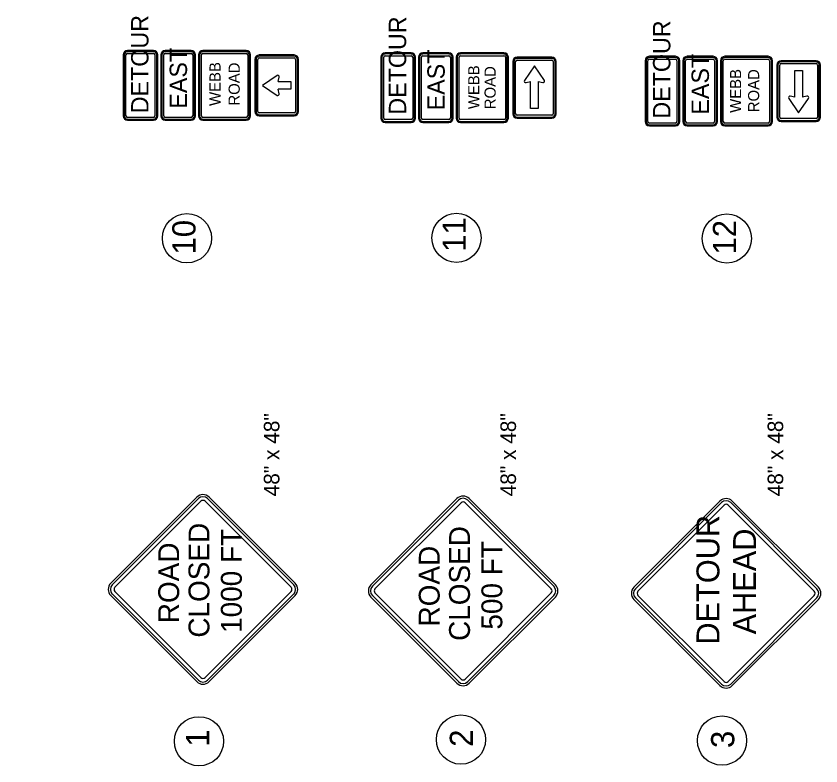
# Model space of a CAD drawing. Extents: x 1123038 to 1172987, y 554419 to 623636.
# Drawn here: x 1123038 to 1128822, y 554419 to 559806 of the extents above; entities that cross this region are included whole.
import ezdxf

# ---------------------------------------------------------------- set-up
doc = ezdxf.new("R2010")
doc.units = 0
doc.layers.add('D_Text_Standard', color=7, linetype='Continuous')
doc.layers.add('Default', color=7, linetype='Continuous')

msp = doc.modelspace()

# ---------------------------------------------------------------- linework, layer by layer
at = {"layer": 'D_Text_Standard'}
for centre in [(1124265.6, 558210), (1126203.5, 558213.5), (1128146.3, 558208.3), (1124352.1, 554596.3), (1126235, 554608.5), (1128111.3, 554601.2)]:
    msp.add_circle(centre, 176.8, dxfattribs=at)
at = {"layer": 'Default'}
for p, q in [((1124025.5, 559558), (1123838, 559558)), ((1124025.5, 559550.2), (1123838, 559550.2)), ((1123838, 559537.1), (1124025.5, 559537.1)), ((1124296.4, 559558), (1124108.9, 559558)), ((1124296.4, 559550.2), (1124108.9, 559550.2)), ((1124108.9, 559537.1), (1124296.4, 559537.1)), ((1124692.2, 559558), (1124379.7, 559558)), ((1124692.2, 559550.2), (1124379.7, 559550.2)), ((1124379.7, 559537.1), (1124692.2, 559537.1)), ((1125877.8, 559541.7), (1125690.3, 559541.7)), ((1125877.8, 559533.9), (1125690.3, 559533.9)), ((1126148.6, 559541.7), (1125961.1, 559541.7)), ((1126148.6, 559533.9), (1125961.1, 559533.9)), ((1126544.4, 559541.7), (1126231.9, 559541.7)), ((1126544.4, 559533.9), (1126231.9, 559533.9)), ((1123806.8, 559526.7), (1123806.8, 559089.2)), ((1123814.6, 559526.7), (1123814.6, 559089.2)), ((1123827.6, 559089.2), (1123827.6, 559526.7)), ((1124035.9, 559526.7), (1124035.9, 559089.2)), ((1124049, 559089.2), (1124049, 559526.7)), ((1124056.8, 559089.2), (1124056.8, 559526.7)), ((1124077.6, 559526.7), (1124077.6, 559089.2)), ((1124085.4, 559526.7), (1124085.4, 559089.2)), ((1124098.4, 559089.2), (1124098.4, 559526.7)), ((1124306.8, 559526.7), (1124306.8, 559089.2)), ((1124319.8, 559089.2), (1124319.8, 559526.7)), ((1124327.6, 559089.2), (1124327.6, 559526.7)), ((1124348.4, 559526.7), (1124348.4, 559089.2)), ((1124356.3, 559526.7), (1124356.3, 559089.2)), ((1124369.3, 559089.2), (1124369.3, 559526.7)), ((1124702.6, 559526.7), (1124702.6, 559089.2)), ((1124715.6, 559089.2), (1124715.6, 559526.7)), ((1124723.4, 559089.2), (1124723.4, 559526.7)), ((1124754.7, 559495.5), (1124754.7, 559120.5)), ((1124762.5, 559495.5), (1124762.5, 559120.5)), ((1124775.5, 559120.5), (1124775.5, 559495.5)), ((1125035.9, 559526.7), (1124785.9, 559526.7)), ((1125035.9, 559518.9), (1124785.9, 559518.9)), ((1124785.9, 559505.9), (1125035.9, 559505.9)), ((1125046.4, 559495.5), (1125046.4, 559120.5)), ((1125059.4, 559120.5), (1125059.4, 559495.5)), ((1125067.2, 559120.5), (1125067.2, 559495.5)), ((1125659, 559510.4), (1125659, 559072.9)), ((1125666.8, 559510.4), (1125666.8, 559072.9)), ((1125679.9, 559072.9), (1125679.9, 559510.4)), ((1125690.3, 559520.8), (1125877.8, 559520.8)), ((1125888.2, 559510.4), (1125888.2, 559072.9)), ((1125901.2, 559072.9), (1125901.2, 559510.4)), ((1125909, 559072.9), (1125909, 559510.4)), ((1125929.9, 559510.4), (1125929.9, 559072.9)), ((1125937.7, 559510.4), (1125937.7, 559072.9)), ((1125950.7, 559072.9), (1125950.7, 559510.4)), ((1125961.1, 559520.8), (1126148.6, 559520.8)), ((1126159, 559510.4), (1126159, 559072.9)), ((1126172, 559072.9), (1126172, 559510.4)), ((1126179.9, 559072.9), (1126179.9, 559510.4)), ((1126200.7, 559510.4), (1126200.7, 559072.9)), ((1126208.5, 559510.4), (1126208.5, 559072.9)), ((1126221.5, 559072.9), (1126221.5, 559510.4)), ((1126231.9, 559520.8), (1126544.4, 559520.8)), ((1126554.9, 559510.4), (1126554.9, 559072.9)), ((1126567.9, 559072.9), (1126567.9, 559510.4)), ((1126575.7, 559072.9), (1126575.7, 559510.4)), ((1126606.9, 559479.2), (1126606.9, 559104.2)), ((1126614.7, 559479.2), (1126614.7, 559104.2)), ((1126627.8, 559104.2), (1126627.8, 559479.2)), ((1126888.2, 559510.4), (1126638.2, 559510.4)), ((1126888.2, 559502.6), (1126638.2, 559502.6)), ((1126638.2, 559489.6), (1126888.2, 559489.6)), ((1126898.6, 559479.2), (1126898.6, 559104.2)), ((1126911.6, 559104.2), (1126911.6, 559479.2)), ((1126919.4, 559104.2), (1126919.4, 559479.2)), ((1127557.9, 559485.9), (1127557.9, 559048.4)), ((1127565.7, 559485.9), (1127565.7, 559048.4)), ((1127578.7, 559048.4), (1127578.7, 559485.9)), ((1127776.6, 559517.2), (1127589.1, 559517.2)), ((1127776.6, 559509.4), (1127589.1, 559509.4)), ((1127589.1, 559496.3), (1127776.6, 559496.3)), ((1127787.1, 559485.9), (1127787.1, 559048.4)), ((1127800.1, 559048.4), (1127800.1, 559485.9)), ((1127807.9, 559048.4), (1127807.9, 559485.9)), ((1127828.7, 559485.9), (1127828.7, 559048.4)), ((1127836.5, 559485.9), (1127836.5, 559048.4)), ((1127849.5, 559048.4), (1127849.5, 559485.9)), ((1128047.5, 559517.2), (1127860, 559517.2)), ((1128047.5, 559509.4), (1127860, 559509.4)), ((1127860, 559496.3), (1128047.5, 559496.3)), ((1128057.9, 559485.9), (1128057.9, 559048.4)), ((1128070.9, 559048.4), (1128070.9, 559485.9)), ((1128078.7, 559048.4), (1128078.7, 559485.9)), ((1128099.5, 559485.9), (1128099.5, 559048.4)), ((1128107.4, 559485.9), (1128107.4, 559048.4)), ((1128120.4, 559048.4), (1128120.4, 559485.9)), ((1128443.3, 559517.2), (1128130.8, 559517.2)), ((1128443.3, 559509.4), (1128130.8, 559509.4)), ((1128130.8, 559496.3), (1128443.3, 559496.3)), ((1128453.7, 559485.9), (1128453.7, 559048.4)), ((1128466.7, 559048.4), (1128466.7, 559485.9)), ((1128474.5, 559048.4), (1128474.5, 559485.9)), ((1128787, 559485.9), (1128537, 559485.9)), ((1128787, 559478.1), (1128537, 559478.1)), ((1126763.2, 559447.9), (1126691.9, 559344.1)), ((1126834.5, 559344.1), (1126763.2, 559447.9)), ((1128505.8, 559454.7), (1128505.8, 559079.7)), ((1128513.6, 559454.7), (1128513.6, 559079.7)), ((1128526.6, 559079.7), (1128526.6, 559454.7)), ((1128537, 559465.1), (1128787, 559465.1)), ((1128634.7, 559415.6), (1128689.4, 559415.6)), ((1128634.7, 559222.9), (1128634.7, 559415.6)), ((1128689.4, 559415.6), (1128689.4, 559222.9)), ((1128797.5, 559454.7), (1128797.5, 559079.7)), ((1128810.5, 559079.7), (1128810.5, 559454.7)), ((1128818.3, 559079.7), (1128818.3, 559454.7)), ((1124913.2, 559379.3), (1124809.4, 559308)), ((1124921.4, 559335.3), (1124928.9, 559368.1)), ((1124809.4, 559308), (1124913.2, 559236.7)), ((1124921.4, 559335.3), (1125012.5, 559335.3)), ((1125012.5, 559335.3), (1125012.5, 559280.6)), ((1126703, 559328.4), (1126735.8, 559335.9)), ((1126735.8, 559143.2), (1126735.8, 559335.9)), ((1126790.5, 559335.9), (1126823.3, 559328.4)), ((1126790.5, 559335.9), (1126790.5, 559143.2)), ((1124928.9, 559247.8), (1124921.4, 559280.6)), ((1125012.5, 559280.6), (1124921.4, 559280.6)), ((1128590.7, 559214.7), (1128662, 559110.9)), ((1128634.7, 559222.9), (1128601.9, 559230.4)), ((1128662, 559110.9), (1128733.4, 559214.7)), ((1128722.2, 559230.4), (1128689.4, 559222.9)), ((1126790.5, 559143.2), (1126735.8, 559143.2)), ((1124025.5, 559078.8), (1123838, 559078.8)), ((1124296.4, 559078.8), (1124108.9, 559078.8)), ((1124692.2, 559078.8), (1124379.7, 559078.8)), ((1125035.9, 559110.1), (1124785.9, 559110.1)), ((1124785.9, 559097), (1125035.9, 559097)), ((1124785.9, 559089.2), (1125035.9, 559089.2)), ((1126888.2, 559093.8), (1126638.2, 559093.8)), ((1126638.2, 559080.7), (1126888.2, 559080.7)), ((1126638.2, 559072.9), (1126888.2, 559072.9)), ((1128787, 559069.3), (1128537, 559069.3)), ((1123838, 559065.8), (1124025.5, 559065.8)), ((1123838, 559058), (1124025.5, 559058)), ((1124108.9, 559065.8), (1124296.4, 559065.8)), ((1124108.9, 559058), (1124296.4, 559058)), ((1124379.7, 559065.8), (1124692.2, 559065.8)), ((1124379.7, 559058), (1124692.2, 559058)), ((1125877.8, 559062.5), (1125690.3, 559062.5)), ((1125690.3, 559049.5), (1125877.8, 559049.5)), ((1125690.3, 559041.7), (1125877.8, 559041.7)), ((1126148.6, 559062.5), (1125961.1, 559062.5)), ((1125961.1, 559049.5), (1126148.6, 559049.5)), ((1125961.1, 559041.7), (1126148.6, 559041.7)), ((1126544.4, 559062.5), (1126231.9, 559062.5)), ((1126231.9, 559049.5), (1126544.4, 559049.5)), ((1126231.9, 559041.7), (1126544.4, 559041.7)), ((1127776.6, 559038), (1127589.1, 559038)), ((1127589.1, 559025), (1127776.6, 559025)), ((1127589.1, 559017.2), (1127776.6, 559017.2)), ((1128047.5, 559038), (1127860, 559038)), ((1127860, 559025), (1128047.5, 559025)), ((1127860, 559017.2), (1128047.5, 559017.2)), ((1128443.3, 559038), (1128130.8, 559038)), ((1128130.8, 559025), (1128443.3, 559025)), ((1128130.8, 559017.2), (1128443.3, 559017.2)), ((1128537, 559056.2), (1128787, 559056.2)), ((1128537, 559048.4), (1128787, 559048.4)), ((1124336.7, 556350.4), (1123718, 555731.7)), ((1125043.8, 555731.7), (1124425.1, 556350.4)), ((1124347.8, 556339.4), (1123729, 555720.7)), ((1123747.5, 555702.3), (1124366.2, 556321)), ((1124395.6, 556321), (1125014.3, 555702.3)), ((1125032.8, 555720.7), (1124414, 556339.4)), ((1126206.4, 556339.5), (1125587.7, 555720.8)), ((1126217.5, 556328.5), (1125598.8, 555709.8)), ((1125617.2, 555691.4), (1126235.9, 556310.1)), ((1126265.4, 556310.1), (1126884.1, 555691.4)), ((1126902.5, 555709.8), (1126283.8, 556328.5)), ((1126913.5, 555720.8), (1126294.8, 556339.5)), ((1128096.7, 556322.1), (1127478, 555703.4)), ((1128107.8, 556311), (1127489.1, 555692.3)), ((1127507.5, 555673.9), (1128126.2, 556292.6)), ((1128155.7, 556292.6), (1128774.4, 555673.9)), ((1128792.8, 555692.3), (1128174.1, 556311)), ((1128803.8, 555703.4), (1128185.1, 556322.1)), ((1123729, 555654.4), (1124347.8, 555035.7)), ((1124366.2, 555054.1), (1123747.5, 555672.8)), ((1125014.3, 555672.8), (1124395.6, 555054.1)), ((1124414, 555035.7), (1125032.8, 555654.4)), ((1126235.9, 555043.2), (1125617.2, 555661.9)), ((1126884.1, 555661.9), (1126265.4, 555043.2)), ((1123718, 555643.3), (1124336.7, 555024.6)), ((1124425.1, 555024.6), (1125043.8, 555643.3)), ((1125587.7, 555632.4), (1126206.4, 555013.7)), ((1125598.8, 555643.5), (1126217.5, 555024.8)), ((1126283.8, 555024.8), (1126902.5, 555643.5)), ((1126294.8, 555013.7), (1126913.5, 555632.4)), ((1127478, 555615), (1128096.7, 554996.3)), ((1127489.1, 555626), (1128107.8, 555007.3)), ((1128126.2, 555025.7), (1127507.5, 555644.4)), ((1128774.4, 555644.4), (1128155.7, 555025.7)), ((1128174.1, 555007.3), (1128792.8, 555626)), ((1128185.1, 554996.3), (1128803.8, 555615))]:
    msp.add_line(p, q, dxfattribs=at)
for centre, radius, start, end in [((1123838, 559526.7), 31.2, 90, 180), ((1123838, 559526.7), 23.4, 90, 180), ((1123838, 559526.7), 10.4, 90, 180), ((1124025.5, 559526.7), 31.2, 0, 90), ((1124025.5, 559526.7), 23.4, 0, 90), ((1124025.5, 559526.7), 10.4, 0, 90), ((1124108.9, 559526.7), 31.2, 90, 180), ((1124108.9, 559526.7), 23.4, 90, 180), ((1124108.9, 559526.7), 10.4, 90, 180), ((1124296.4, 559526.7), 31.2, 0, 90), ((1124296.4, 559526.7), 23.4, 0, 90), ((1124296.4, 559526.7), 10.4, 0, 90), ((1124379.7, 559526.7), 31.2, 90, 180), ((1124379.7, 559526.7), 23.4, 90, 180), ((1124379.7, 559526.7), 10.4, 90, 180), ((1124692.2, 559526.7), 31.2, 0, 90), ((1124692.2, 559526.7), 23.4, 0, 90), ((1124692.2, 559526.7), 10.4, 0, 90), ((1125690.3, 559510.4), 31.2, 90, 180), ((1125690.3, 559510.4), 23.4, 90, 180), ((1125877.8, 559510.4), 31.2, 0, 90), ((1125877.8, 559510.4), 23.4, 0, 90), ((1125961.1, 559510.4), 31.2, 90, 180), ((1125961.1, 559510.4), 23.4, 90, 180), ((1126148.6, 559510.4), 31.2, 0, 90), ((1126148.6, 559510.4), 23.4, 0, 90), ((1126231.9, 559510.4), 31.2, 90, 180), ((1126231.9, 559510.4), 23.4, 90, 180), ((1126544.4, 559510.4), 31.2, 0, 90), ((1126544.4, 559510.4), 23.4, 0, 90), ((1124785.9, 559495.5), 31.2, 90, 180), ((1124785.9, 559495.5), 23.4, 90, 180), ((1124785.9, 559495.5), 10.4, 90, 180), ((1125035.9, 559495.5), 31.2, 0, 90), ((1125035.9, 559495.5), 23.4, 0, 90), ((1125035.9, 559495.5), 10.4, 0, 90), ((1125690.3, 559510.4), 10.4, 90, 180), ((1125877.8, 559510.4), 10.4, 0, 90), ((1125961.1, 559510.4), 10.4, 90, 180), ((1126148.6, 559510.4), 10.4, 0, 90), ((1126231.9, 559510.4), 10.4, 90, 180), ((1126544.4, 559510.4), 10.4, 0, 90), ((1126638.2, 559479.2), 31.2, 90, 180), ((1126638.2, 559479.2), 23.4, 90, 180), ((1126638.2, 559479.2), 10.4, 90, 180), ((1126888.2, 559479.2), 31.2, 0, 90), ((1126888.2, 559479.2), 23.4, 0, 90), ((1126888.2, 559479.2), 10.4, 0, 90), ((1127589.1, 559485.9), 31.2, 90, 180), ((1127589.1, 559485.9), 23.4, 90, 180), ((1127589.1, 559485.9), 10.4, 90, 180), ((1127776.6, 559485.9), 31.2, 0, 90), ((1127776.6, 559485.9), 23.4, 0, 90), ((1127776.6, 559485.9), 10.4, 0, 90), ((1127860, 559485.9), 31.2, 90, 180), ((1127860, 559485.9), 23.4, 90, 180), ((1127860, 559485.9), 10.4, 90, 180), ((1128047.5, 559485.9), 31.2, 0, 90), ((1128047.5, 559485.9), 23.4, 0, 90), ((1128047.5, 559485.9), 10.4, 0, 90), ((1128130.8, 559485.9), 31.2, 90, 180), ((1128130.8, 559485.9), 23.4, 90, 180), ((1128130.8, 559485.9), 10.4, 90, 180), ((1128443.3, 559485.9), 31.2, 0, 90), ((1128443.3, 559485.9), 23.4, 0, 90), ((1128443.3, 559485.9), 10.4, 0, 90), ((1128537, 559454.7), 31.2, 90, 180), ((1128537, 559454.7), 23.4, 90, 180), ((1128787, 559454.7), 31.2, 0, 90), ((1128787, 559454.7), 23.4, 0, 90), ((1128537, 559454.7), 10.4, 90, 180), ((1128787, 559454.7), 10.4, 0, 90), ((1124918.8, 559370.5), 10.4, 347.0497, 122.2757), ((1126700.7, 559338.5), 10.4, 147.7244, 282.9503), ((1126825.7, 559338.5), 10.4, 257.0497, 32.2757), ((1124918.8, 559245.5), 10.4, 237.7244, 12.9504), ((1128599.5, 559220.3), 10.4, 77.0497, 212.2757), ((1128724.5, 559220.3), 10.4, 327.7244, 102.9504), ((1123838, 559089.2), 31.2, 180, 270), ((1123838, 559089.2), 23.4, 180, 270), ((1123838, 559089.2), 10.4, 180, 270), ((1124025.5, 559089.2), 31.2, 270, 0), ((1124025.5, 559089.2), 23.4, 270, 0), ((1124025.5, 559089.2), 10.4, 270, 0), ((1124108.9, 559089.2), 31.2, 180, 270), ((1124108.9, 559089.2), 23.4, 180, 270), ((1124108.9, 559089.2), 10.4, 180, 270), ((1124296.4, 559089.2), 31.2, 270, 0), ((1124296.4, 559089.2), 23.4, 270, 0), ((1124296.4, 559089.2), 10.4, 270, 0), ((1124379.7, 559089.2), 31.2, 180, 270), ((1124379.7, 559089.2), 23.4, 180, 270), ((1124379.7, 559089.2), 10.4, 180, 270), ((1124692.2, 559089.2), 31.2, 270, 0), ((1124692.2, 559089.2), 23.4, 270, 0), ((1124692.2, 559089.2), 10.4, 270, 0), ((1124785.9, 559120.5), 31.2, 180, 270), ((1124785.9, 559120.5), 23.4, 180, 270), ((1124785.9, 559120.5), 10.4, 180, 270), ((1125035.9, 559120.5), 31.2, 270, 0), ((1125035.9, 559120.5), 23.4, 270, 0), ((1125035.9, 559120.5), 10.4, 270, 0), ((1125690.3, 559072.9), 31.2, 180, 270), ((1125690.3, 559072.9), 23.4, 180, 270), ((1125690.3, 559072.9), 10.4, 180, 270), ((1125877.8, 559072.9), 31.2, 270, 0), ((1125877.8, 559072.9), 23.4, 270, 0), ((1125877.8, 559072.9), 10.4, 270, 0), ((1125961.1, 559072.9), 31.2, 180, 270), ((1125961.1, 559072.9), 23.4, 180, 270), ((1125961.1, 559072.9), 10.4, 180, 270), ((1126148.6, 559072.9), 31.2, 270, 0), ((1126148.6, 559072.9), 23.4, 270, 0), ((1126148.6, 559072.9), 10.4, 270, 0), ((1126231.9, 559072.9), 31.2, 180, 270), ((1126231.9, 559072.9), 23.4, 180, 270), ((1126231.9, 559072.9), 10.4, 180, 270), ((1126544.4, 559072.9), 31.2, 270, 0), ((1126544.4, 559072.9), 23.4, 270, 0), ((1126544.4, 559072.9), 10.4, 270, 0), ((1126638.2, 559104.2), 31.2, 180, 270), ((1126638.2, 559104.2), 23.4, 180, 270), ((1126638.2, 559104.2), 10.4, 180, 270), ((1126888.2, 559104.2), 31.2, 270, 0), ((1126888.2, 559104.2), 23.4, 270, 0), ((1126888.2, 559104.2), 10.4, 270, 0), ((1128537, 559079.7), 31.2, 180, 270), ((1128537, 559079.7), 23.4, 180, 270), ((1128537, 559079.7), 10.4, 180, 270), ((1128787, 559079.7), 31.2, 270, 0), ((1128787, 559079.7), 23.4, 270, 0), ((1128787, 559079.7), 10.4, 270, 0), ((1127589.1, 559048.4), 31.2, 180, 270), ((1127589.1, 559048.4), 23.4, 180, 270), ((1127589.1, 559048.4), 10.4, 180, 270), ((1127776.6, 559048.4), 31.2, 270, 0), ((1127776.6, 559048.4), 23.4, 270, 0), ((1127776.6, 559048.4), 10.4, 270, 0), ((1127860, 559048.4), 31.2, 180, 270), ((1127860, 559048.4), 23.4, 180, 270), ((1127860, 559048.4), 10.4, 180, 270), ((1128047.5, 559048.4), 31.2, 270, 0), ((1128047.5, 559048.4), 23.4, 270, 0), ((1128047.5, 559048.4), 10.4, 270, 0), ((1128130.8, 559048.4), 31.2, 180, 270), ((1128130.8, 559048.4), 23.4, 180, 270), ((1128130.8, 559048.4), 10.4, 180, 270), ((1128443.3, 559048.4), 31.2, 270, 0), ((1128443.3, 559048.4), 23.4, 270, 0), ((1128443.3, 559048.4), 10.4, 270, 0), ((1124380.9, 556306.2), 62.5, 45, 135), ((1124380.9, 556306.2), 46.9, 45, 135), ((1126250.6, 556295.3), 62.5, 45, 135), ((1124380.9, 556306.2), 20.8, 45, 135), ((1126250.6, 556295.3), 46.9, 45, 135), ((1126250.6, 556295.3), 20.8, 45, 135), ((1128140.9, 556277.9), 62.5, 45, 135), ((1128140.9, 556277.9), 46.9, 45, 135), ((1128140.9, 556277.9), 20.8, 45, 135), ((1123762.2, 555687.5), 62.5, 135, 225), ((1123762.2, 555687.5), 46.9, 135, 225), ((1124999.6, 555687.5), 46.9, 315, 45), ((1124999.6, 555687.5), 62.5, 315, 45), ((1125631.9, 555676.6), 62.5, 135, 225), ((1126869.3, 555676.6), 62.5, 315, 45), ((1123762.2, 555687.5), 20.8, 135, 225), ((1124999.6, 555687.5), 20.8, 315, 45), ((1125631.9, 555676.6), 46.9, 135, 225), ((1125631.9, 555676.6), 20.8, 135, 225), ((1126869.3, 555676.6), 20.8, 315, 45), ((1126869.3, 555676.6), 46.9, 315, 45), ((1127522.2, 555659.2), 62.5, 135, 225), ((1127522.2, 555659.2), 46.9, 135, 225), ((1127522.2, 555659.2), 20.8, 135, 225), ((1128759.6, 555659.2), 20.8, 315, 45), ((1128759.6, 555659.2), 46.9, 315, 45), ((1128759.6, 555659.2), 62.5, 315, 45), ((1124380.9, 555068.8), 62.5, 225, 315), ((1124380.9, 555068.8), 46.9, 225, 315), ((1124380.9, 555068.8), 20.8, 225, 315), ((1126250.6, 555057.9), 46.9, 225, 315), ((1126250.6, 555057.9), 20.8, 225, 315), ((1128140.9, 555040.5), 20.8, 225, 315), ((1126250.6, 555057.9), 62.5, 225, 315), ((1128140.9, 555040.5), 62.5, 225, 315), ((1128140.9, 555040.5), 46.9, 225, 315)]:
    msp.add_arc(centre, radius, start, end, dxfattribs=at)

# ---------------------------------------------------------------- texts
at = {"layer": 'D_Text_Standard'}
for s, height, p in [('10', 167.06, (1124327.2, 558093.4)), ('11', 167.06, (1126269.6, 558112.6)), ('12', 167.06, (1128212.8, 558093.2)), ('48" x 48"', 111.99, (1124930.3, 556355.9)), ('48" x 48"', 111.99, (1126630.6, 556355.9)), ('48" x 48"', 111.99, (1128551, 556355.9)), ('1', 167.1, (1124426.2, 554557.2)), ('2', 167.1, (1126321.8, 554556.5)), ('3', 167.1, (1128199.7, 554547.6))]:
    msp.add_text(s, height=height, rotation=90, dxfattribs=at).set_placement(p)
at = {"layer": 'Default'}
for s, height, p in [('DETOUR', 125, (1123989.2, 559108.1)), ('DETOUR', 125, (1125841.4, 559098.1)), ('DETOUR', 125, (1127740.3, 559069.5)), ('EAST', 125, (1124266.3, 559141.2)), ('EAST', 125, (1126118.5, 559129)), ('EAST', 125, (1128017.4, 559098.5)), ('WEBB', 80, (1124507.6, 559160.7)), ('ROAD', 80, (1124645.2, 559163.2)), ('WEBB', 80, (1126367.2, 559137.6)), ('ROAD', 80, (1126484.6, 559137.3)), ('WEBB', 80, (1128248.6, 559111.2)), ('ROAD', 80, (1128378.5, 559115.5)), ('DETOUR', 165, (1128092.8, 555290.7)), ('CLOSED', 150, (1124427.2, 555340.9)), ('1000 FT', 150, (1124659.8, 555375)), ('CLOSED', 150, (1126299.6, 555317.3)), ('AHEAD', 165, (1128355.9, 555364.3)), ('ROAD', 150, (1124209.5, 555444.7)), ('500 FT', 150, (1126532.2, 555398.6)), ('ROAD', 150, (1126081.9, 555421.2)), ('ROAD', 0.0003, (1123037.7, 555421.2)), ('CLOSED', 0.0003, (1124387.7, 555421.2)), ('ROAD', 0.0003, (1124910.1, 555397.6)), ('500 FT', 0.0003, (1125737.7, 555421.2)), ('CLOSED', 0.0003, (1126260.1, 555397.6)), ('500 FT', 0.0003, (1127610.1, 555397.6))]:
    msp.add_text(s, height=height, rotation=90, dxfattribs=at).set_placement(p)

doc.saveas('drawing.dxf')
